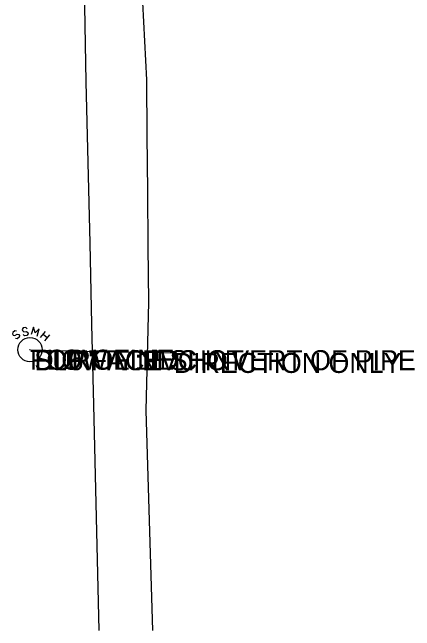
# Model space of a CAD drawing. Extents: x 1800653 to 1804042, y 522635 to 523313.
# Drawn here: x 1802925.2 to 1803025.6, y 522699.6 to 522853.9 of the extents above; entities that cross this region are included whole.
import ezdxf

# ---------------------------------------------------------------- set-up
doc = ezdxf.new("R2010")
doc.units = 0
for name, color, linetype in [('S_GRAVEL_ROAD', 7, 'Continuous'), ('S_GRD_PT_SYM', 7, 'Continuous'), ('S_MANHOLE_ANNOT', 7, 'Continuous'), ('S_MISC_TOPO_POINT', 7, 'Continuous'), ('S_SANITARY_SEWER', 7, 'Continuous'), ('S_SANITARY_SEWER_ANNOT', 7, 'Continuous'), ('S_UTL_PT_SYM', 7, 'Continuous')]:
    doc.layers.add(name, color=color, linetype=linetype)

msp = doc.modelspace()

# ---------------------------------------------------------------- linework, layer by layer
at = {"layer": 'S_GRAVEL_ROAD'}
for points in [[(1802954.81, 522965.58), (1802955.31, 522945.54), (1802955.81, 522925.5), (1802956.03, 522905.55), (1802956.24, 522885.61), (1802957.46, 522861.32), (1802958.68, 522837.04), (1802958.8, 522823.18), (1802958.92, 522809.31), (1802959.04, 522795.45), (1802959.17, 522781.58), (1802958.84, 522768.07), (1802958.52, 522754.56), (1802958.93, 522740.82), (1802959.34, 522727.07), (1802959.75, 522713.32), (1802960.16, 522699.58)], [(1802939.44, 522964.79), (1802940.92, 522943.92), (1802942.41, 522923.04), (1802942.58, 522903.43), (1802942.74, 522883.82), (1802943.15, 522860.2), (1802943.56, 522836.59), (1802944.03, 522816.43), (1802944.5, 522796.27), (1802944.97, 522776.11), (1802945.44, 522755.95), (1802945.78, 522741.87), (1802946.11, 522727.8), (1802946.44, 522713.72), (1802946.77, 522699.64)]]:
    msp.add_lwpolyline(points, dxfattribs=at)
at = {"layer": 'S_GRD_PT_SYM'}
msp.add_lwpolyline([(1802930.67, 522769.59), (1802930.67, 522769.64), (1802930.67, 522769.59), (1802930.62, 522769.59), (1802930.67, 522769.59), (1802930.67, 522769.54), (1802930.67, 522769.59), (1802930.72, 522769.59)], dxfattribs=at)
at = {"layer": 'S_SANITARY_SEWER'}
for p, q in [((1802925.81, 522774.41), (1802925.27, 522774.02)), ((1802926.24, 522774.33), (1802925.81, 522774.41)), ((1802932.24, 522772.78), (1802933.48, 522774.25)), ((1802925.27, 522774.02), (1802925.19, 522773.63)), ((1802925.19, 522773.63), (1802925.38, 522773.36)), ((1802925.38, 522773.36), (1802925.81, 522773.24)), ((1802925.81, 522773.24), (1802926.35, 522773.59)), ((1802926.35, 522773.59), (1802926.82, 522773.51)), ((1802926.89, 522772.82), (1802926.35, 522772.43)), ((1802926.82, 522773.51), (1802926.97, 522773.24)), ((1802926.97, 522773.24), (1802926.89, 522772.82)), ((1802932.9, 522773.55), (1802933.87, 522772.74)), ((1802934.45, 522773.44), (1802933.21, 522771.96)), ((1802926.35, 522772.43), (1802925.96, 522772.51)), ((1802930.67, 522769.59), (1802965.5, 522768.91))]:
    msp.add_line(p, q, dxfattribs=at)
for points in [[(1802928.91, 522774.95), (1802928.56, 522775.22), (1802927.9, 522775.14), (1802927.67, 522774.79), (1802927.71, 522774.48), (1802928.06, 522774.17), (1802928.68, 522774.29), (1802929.06, 522773.98), (1802929.1, 522773.67), (1802928.83, 522773.28), (1802928.21, 522773.2), (1802927.86, 522773.48)], [(1802931.35, 522773.09), (1802931.89, 522774.95), (1802930.85, 522773.94), (1802930.46, 522775.37), (1802929.92, 522773.51)]]:
    msp.add_lwpolyline(points, dxfattribs=at)
msp.add_circle((1802929.59, 522769.71), 3.05, dxfattribs=at)
at = {"layer": 'S_UTL_PT_SYM'}
for points in [[(1802929.59, 522769.71), (1802929.59, 522769.76), (1802929.59, 522769.71), (1802929.54, 522769.71), (1802929.59, 522769.71), (1802929.59, 522769.66), (1802929.59, 522769.71), (1802929.64, 522769.71)], [(1802930.67, 522769.59), (1802930.67, 522769.64), (1802930.67, 522769.59), (1802930.62, 522769.59), (1802930.67, 522769.59), (1802930.67, 522769.54), (1802930.67, 522769.59), (1802930.72, 522769.59)], [(1802965.5, 522768.91), (1802965.5, 522768.96), (1802965.5, 522768.91), (1802965.45, 522768.91), (1802965.5, 522768.91), (1802965.5, 522768.86), (1802965.5, 522768.91), (1802965.55, 522768.91)]]:
    msp.add_lwpolyline(points, dxfattribs=at)

# ---------------------------------------------------------------- texts
at = {"layer": 'S_MANHOLE_ANNOT'}
msp.add_text('FLOW LINE', height=5, dxfattribs=at).set_placement((1802929.59, 522764.71))
at = {"layer": 'S_MISC_TOPO_POINT'}
msp.add_text('SURFACE SHOT', height=5, dxfattribs=at).set_placement((1802930.67, 522764.59))
at = {"layer": 'S_SANITARY_SEWER_ANNOT'}
for s, p in [('TOP OF LID', (1802929.59, 522764.71)), ('DI:6" TY:PVC INVERT OF PIPE', (1802930.67, 522764.59)), ('DIRECTION ONLY', (1802965.5, 522763.91))]:
    msp.add_text(s, height=5, dxfattribs=at).set_placement(p)

doc.saveas('drawing.dxf')
